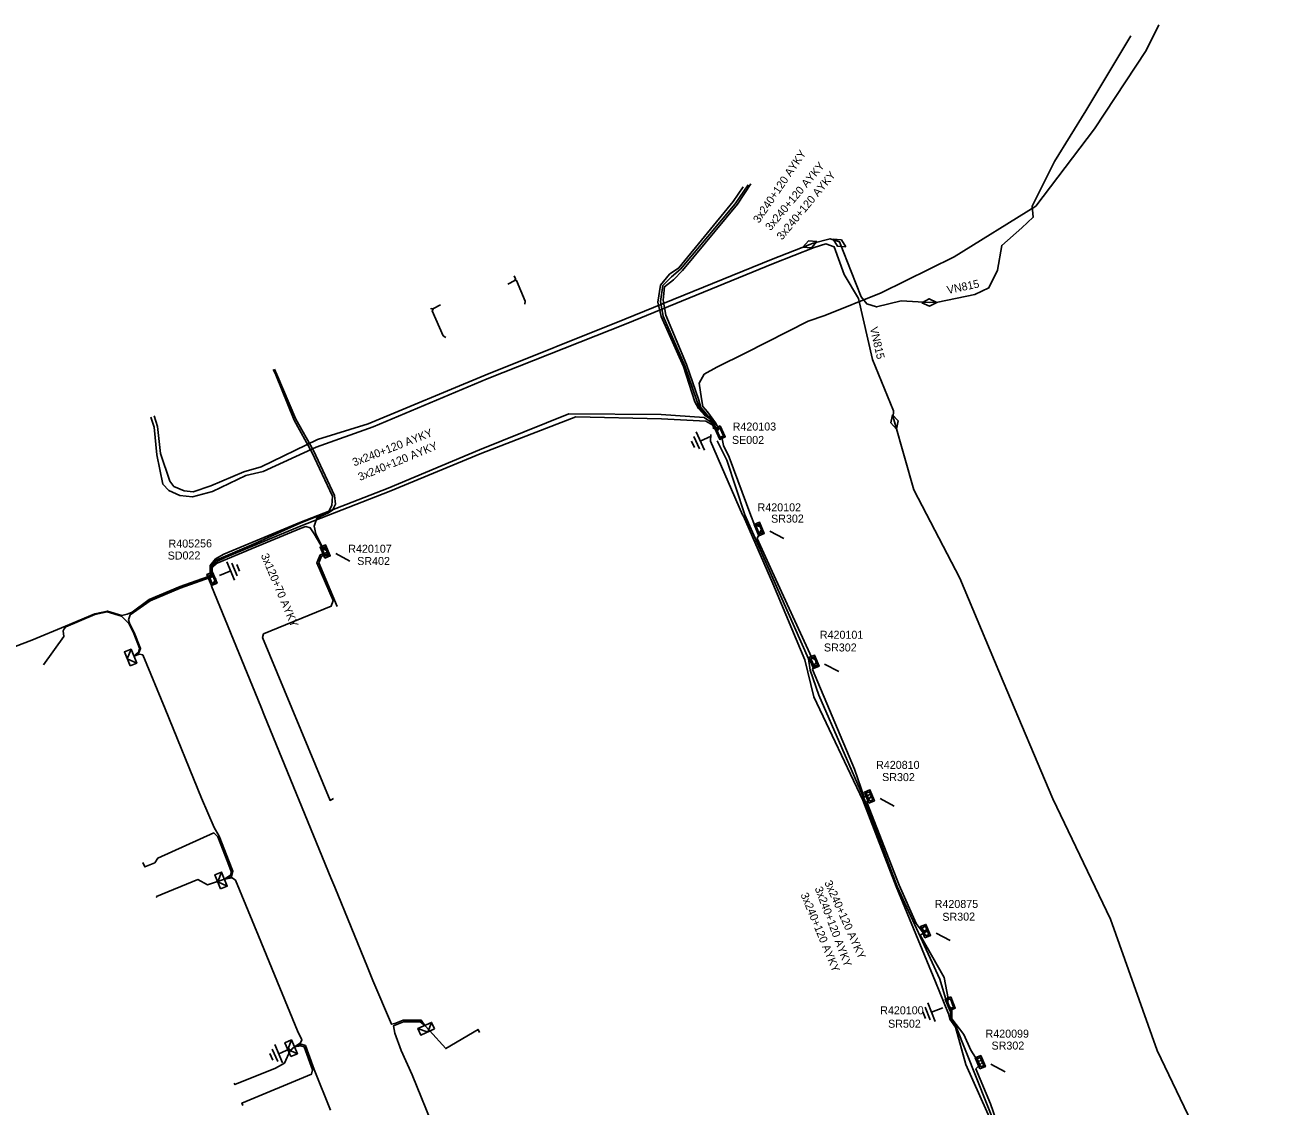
# Model space of a CAD drawing. Extents: x -540028 to -538776, y -1157064 to -1155670.
# Drawn here: x -539610.5 to -539454.6, y -1155813.9 to -1155678.8 of the extents above; entities that cross this region are included whole.
import ezdxf

# ---------------------------------------------------------------- set-up
doc = ezdxf.new("R2010")
doc.units = 0
for name, color, linetype in [('Vrstva 15', 7, 'Continuous'), ('Vrstva 19', 7, 'Continuous'), ('Vrstva 2', 7, 'Continuous'), ('Vrstva 28', 7, 'Continuous'), ('Vrstva 29', 7, 'Continuous'), ('Vrstva 30', 7, 'Continuous'), ('Vrstva 31', 7, 'Continuous'), ('Vrstva 5', 7, 'Continuous'), ('Vrstva 52', 7, 'Continuous'), ('Vrstva 59', 7, 'Continuous'), ('Vrstva 6', 7, 'Continuous'), ('Vrstva 7', 7, 'Continuous')]:
    doc.layers.add(name, color=color, linetype=linetype)

# ---------------------------------------------------------------- blocks, each defined once
blk = doc.blocks.new('17')
at = {"layer": 'Vrstva 2'}
blk.add_lwpolyline([(-1.875, 0), (0, 0.9375), (1.875, 0), (0, -0.9375)], close=True, dxfattribs=at)
blk = doc.blocks.new('132')
at = {"layer": 'Vrstva 2'}
for points in [[(-1.5, 1.5), (1.5, 1.5), (1.5, 0), (-1.5, 0)], [(-1.1, 1.2), (1.1, 1.2), (1.1, 0.3), (-1.1, 0.3)]]:
    blk.add_lwpolyline(points, close=True, dxfattribs=at)
blk = doc.blocks.new('23')
at = {"layer": 'Vrstva 2'}
blk.add_lwpolyline([(1.875, -1.8), (-1.875, -1.8), (-1.875, 0), (1.875, 0)], close=True, dxfattribs=at)
blk.add_lwpolyline([(1.875, 0), (0, -1.8), (-1.875, 0)], dxfattribs=at)
blk = doc.blocks.new('11')
at = {"layer": 'Vrstva 2'}
for p, q in [((0, -4.3), (0, -1.3)), ((-2.5, -4.3), (2.5, -4.3)), ((-1.7, -5.3), (1.7, -5.3)), ((-0.9, -6.3), (0.9, -6.3))]:
    blk.add_line(p, q, dxfattribs=at)

msp = doc.modelspace()

# ---------------------------------------------------------------- linework, layer by layer
at = {"layer": 'Vrstva 5'}
for points in [[(-539468.86, -1155678.76), (-539470.45, -1155681.97), (-539476.89, -1155691.74), (-539484.25, -1155701.39), (-539494.42, -1155707.72), (-539503.56, -1155712.23), (-539510.61, -1155715.06), (-539512.66, -1155715.76), (-539520.48, -1155719.75), (-539524.11, -1155721.52), (-539525.68, -1155722.4), (-539526.28, -1155723.51), (-539526.02, -1155725.46), (-539525.83, -1155726.44), (-539525.25, -1155727.12), (-539524.27, -1155728.46), (-539523.83, -1155729.24), (-539524.12, -1155729.6)], [(-539497.53, -1155713.45), (-539496.48, -1155713.42), (-539491.84, -1155712.45), (-539490.09, -1155711.59), (-539489.04, -1155709.39), (-539488.49, -1155706.31), (-539485.99, -1155704.13), (-539484.55, -1155702.79), (-539484.68, -1155701.4), (-539481.91, -1155695.84), (-539478, -1155689.51), (-539472.36, -1155680.12)], [(-539524.39, -1155729.17), (-539524.4, -1155728.7), (-539525.01, -1155727.93), (-539525.64, -1155727.54), (-539526.4, -1155726.69), (-539526.82, -1155725.84), (-539528.25, -1155721.46), (-539531.05, -1155715.21), (-539531.46, -1155713.41), (-539531.13, -1155711.26), (-539530.01, -1155709.92), (-539528.83, -1155709.12), (-539522.06, -1155700.83), (-539520.8, -1155698.97)], [(-539520.17, -1155698.72), (-539521.79, -1155701.12), (-539528.61, -1155709.26), (-539529.76, -1155710.25), (-539530.84, -1155711.33), (-539531.13, -1155713.3), (-539530.78, -1155715.13), (-539528.1, -1155721.34), (-539526.59, -1155725.73), (-539526.24, -1155726.6), (-539525.49, -1155727.5), (-539524.94, -1155727.89), (-539524.37, -1155728.64), (-539524.35, -1155729.15)], [(-539524.31, -1155729.17), (-539524.34, -1155728.58), (-539524.88, -1155727.85), (-539525.36, -1155727.43), (-539526.09, -1155726.55), (-539526.34, -1155725.63), (-539527.9, -1155721.17), (-539530.47, -1155715.01), (-539530.81, -1155713.14), (-539530.61, -1155711.48), (-539529.52, -1155710.63), (-539528.39, -1155709.44), (-539521.49, -1155701.14), (-539519.85, -1155698.6)], [(-539512.46, -1155706.18), (-539512.05, -1155706.02), (-539509.94, -1155705.47), (-539508.76, -1155705.88), (-539508.68, -1155706.08)], [(-539501.89, -1155728.36), (-539502.06, -1155727.76), (-539502.01, -1155726.97), (-539504.63, -1155720.56), (-539506.39, -1155712.94), (-539508.2, -1155709.96), (-539509.43, -1155706.47), (-539510.46, -1155706.12), (-539511.93, -1155706.57), (-539516.99, -1155708.58), (-539535.42, -1155716.09), (-539552.79, -1155723), (-539567.02, -1155728.99), (-539574.14, -1155731.51), (-539580.78, -1155734.54), (-539582.92, -1155735.05), (-539587.1, -1155737.06), (-539589.6, -1155737.71), (-539591.2, -1155737.58), (-539592.57, -1155736.94), (-539593.29, -1155736.16), (-539594.06, -1155732.47), (-539594.41, -1155729.04), (-539594.8, -1155727.76)], [(-539594.37, -1155727.6), (-539593.97, -1155728.94), (-539593.6, -1155732.32), (-539592.45, -1155735.75), (-539591.92, -1155736.44), (-539590.63, -1155736.96), (-539589.53, -1155737.11), (-539587.3, -1155736.36), (-539583.19, -1155734.59), (-539581.03, -1155733.98), (-539573.97, -1155730.58), (-539567.65, -1155728.6), (-539553.04, -1155722.51), (-539535.59, -1155715.53), (-539517.24, -1155708.08), (-539512.46, -1155706.18)], [(-539508.68, -1155706.08), (-539507.32, -1155709.55), (-539506.06, -1155712.73), (-539505.37, -1155713.61), (-539504.13, -1155714), (-539501.06, -1155713.25), (-539497.53, -1155713.45)], [(-539549.4, -1155710.1), (-539549.23, -1155710.48), (-539549.32, -1155710.67), (-539549.12, -1155710.69), (-539548.03, -1155713.28)], [(-539558.27, -1155717.61), (-539559.67, -1155714.48), (-539559.49, -1155714.21), (-539559.79, -1155714.22), (-539559.83, -1155714.15)], [(-539579.53, -1155721.82), (-539579.21, -1155722.49), (-539576.9, -1155728.13), (-539574.68, -1155732.16), (-539572.12, -1155737.66), (-539572.19, -1155738.79), (-539572.62, -1155739.58), (-539576.06, -1155740.99), (-539582.28, -1155743.76), (-539586.65, -1155745.66), (-539587.31, -1155746.42), (-539587.29, -1155747.24), (-539587.09, -1155747.35), (-539587.02, -1155747.32)], [(-539579.37, -1155721.76), (-539579.05, -1155722.43), (-539576.71, -1155728.01), (-539574.49, -1155731.93), (-539571.85, -1155737.55), (-539571.72, -1155738.64), (-539572.09, -1155739.4), (-539572.59, -1155739.73), (-539574.06, -1155740.4), (-539574.41, -1155741.39), (-539574.21, -1155742.34), (-539573.37, -1155744), (-539572.73, -1155744.35)], [(-539524.41, -1155729.18), (-539524.46, -1155728.7), (-539524.76, -1155728.42), (-539525.69, -1155727.81), (-539531.04, -1155727.45), (-539542.57, -1155727.37), (-539553.73, -1155731.87), (-539565.17, -1155736.65), (-539576.17, -1155740.92), (-539585.67, -1155744.89), (-539586.72, -1155745.46), (-539587.4, -1155746.32), (-539587.38, -1155747.19), (-539587.07, -1155747.41), (-539586.99, -1155747.38)], [(-539524.54, -1155729.23), (-539524.49, -1155729.15), (-539524.61, -1155728.75), (-539525.47, -1155728.28), (-539531.01, -1155727.98), (-539541.7, -1155727.74), (-539553.45, -1155732.27), (-539565.03, -1155737.04), (-539576.03, -1155741.33), (-539585.5, -1155745.29), (-539586.56, -1155745.82), (-539587.22, -1155746.59), (-539587.18, -1155747.04), (-539587.14, -1155747.14), (-539587.11, -1155747.17)], [(-539450.64, -1155871.22), (-539448.38, -1155870.37), (-539445.91, -1155869.51), (-539445.16, -1155868.63), (-539444.2, -1155867.88), (-539444.08, -1155866.88), (-539445.32, -1155863.06), (-539447.87, -1155858.8), (-539451.16, -1155849.36), (-539456.5, -1155836.11), (-539463.8, -1155817.93), (-539469.08, -1155806.9), (-539474.9, -1155790.51), (-539482.11, -1155775.46), (-539488.3, -1155760.82), (-539493.72, -1155747.89), (-539499.46, -1155736.84), (-539501.89, -1155728.36)], [(-539487.91, -1155820.03), (-539492.98, -1155808.65), (-539494.29, -1155804), (-539494.99, -1155803), (-539495.16, -1155802.35), (-539496.77, -1155798.32), (-539501.7, -1155786.4), (-539505.84, -1155775.62), (-539511.98, -1155762.7), (-539513.08, -1155758.08), (-539517.09, -1155748.54), (-539520.74, -1155740.13), (-539520.87, -1155739.97), (-539524.87, -1155730.77), (-539524.85, -1155729.93)], [(-539518.52, -1155741.52), (-539519.38, -1155741.23), (-539519.84, -1155740.06), (-539522.55, -1155732.78), (-539523.27, -1155731.32), (-539523.44, -1155730.47), (-539523.94, -1155729.99)], [(-539524.05, -1155730.71), (-539522.86, -1155733.16), (-539520.58, -1155739.97), (-539512.64, -1155757.97), (-539512.43, -1155759.39), (-539511.36, -1155762.53), (-539505.62, -1155775.68), (-539501.55, -1155786.41), (-539496.23, -1155797.99), (-539495.41, -1155800.77)], [(-539572.68, -1155744.48), (-539573.27, -1155744.25), (-539574.38, -1155742.37), (-539574.89, -1155741.59), (-539575.43, -1155741.45), (-539576.04, -1155741.66), (-539582.15, -1155744.18), (-539586.52, -1155746.02), (-539587.16, -1155746.58), (-539587.15, -1155747.08), (-539587.12, -1155747.1)], [(-539511.67, -1155758.13), (-539512.23, -1155757.85), (-539517.17, -1155747.04), (-539519.05, -1155742.95), (-539518.45, -1155741.7)], [(-539586.96, -1155747.46), (-539587, -1155747.48), (-539591.15, -1155748.94), (-539595.01, -1155750.56), (-539597.12, -1155752.13), (-539597.76, -1155752.38), (-539598.44, -1155752.54), (-539600.23, -1155752), (-539601.81, -1155752.35), (-539605.48, -1155753.89), (-539609.69, -1155755.65), (-539615.1, -1155757.69)], [(-539586.81, -1155747.59), (-539591.15, -1155749.14), (-539594.9, -1155750.72), (-539597.38, -1155752.46), (-539597.59, -1155753.08), (-539597.48, -1155753.52), (-539596.9, -1155754.66), (-539596.08, -1155756.66), (-539596.3, -1155757.2), (-539596.92, -1155757.63), (-539596.23, -1155757.39), (-539595.82, -1155757.49), (-539593.02, -1155764.23), (-539588.47, -1155775.39), (-539586.88, -1155779.05), (-539586.25, -1155780.12), (-539585.02, -1155783.33), (-539584.57, -1155784.51), (-539584.71, -1155785.2), (-539585.61, -1155785.49), (-539584.65, -1155785.35), (-539584.21, -1155785.64), (-539581.36, -1155792.58), (-539578.71, -1155799.08), (-539576.48, -1155804.44), (-539575.93, -1155805.56), (-539576.09, -1155805.97), (-539576.86, -1155806.46), (-539576.03, -1155806.13), (-539575.5, -1155806.3), (-539574.42, -1155809.28), (-539572.35, -1155814.38)], [(-539559.28, -1155817.03), (-539562.16, -1155809.96), (-539563.51, -1155806.9), (-539564.33, -1155804.74), (-539564.49, -1155803.85), (-539563.24, -1155803.33), (-539561.14, -1155803.34), (-539560.58, -1155803.78), (-539561.02, -1155803.14), (-539563.28, -1155803.13), (-539564.31, -1155803.53), (-539564.75, -1155803.64), (-539567.05, -1155798.18), (-539567.75, -1155796.49), (-539571.82, -1155786.5), (-539572.3, -1155785.33), (-539580.59, -1155765.09), (-539581.07, -1155763.93), (-539587.21, -1155748.88), (-539586.66, -1155747.94)], [(-539504.78, -1155774.85), (-539505.69, -1155775.25), (-539506.88, -1155771.75), (-539512.15, -1155759.3), (-539511.88, -1155758.72), (-539511.59, -1155758.31)], [(-539497.73, -1155791.78), (-539498.45, -1155792.04), (-539499.18, -1155791.03), (-539501.33, -1155786.24), (-539505.37, -1155775.88), (-539504.72, -1155775.01)], [(-539495.32, -1155801.01), (-539495.26, -1155800.99), (-539495.17, -1155800.41), (-539495.69, -1155797.79), (-539498.7, -1155792.48), (-539497.68, -1155791.92)], [(-539490.88, -1155808.16), (-539491.47, -1155808.23), (-539492.36, -1155806.88), (-539493.24, -1155804.91), (-539494.74, -1155802.94), (-539494.72, -1155802.01), (-539495, -1155801.44), (-539495.24, -1155801.11), (-539495.28, -1155801.12)], [(-539494.98, -1155801.92), (-539494.9, -1155802.1), (-539494.9, -1155802.94), (-539494.17, -1155803.94), (-539487.8, -1155819.99), (-539486.51, -1155822.3), (-539485.16, -1155826.12), (-539484.76, -1155827.34), (-539480.87, -1155836.78), (-539479.08, -1155841.24), (-539478.26, -1155843.91), (-539475.43, -1155849.76), (-539472.96, -1155857.03), (-539471.7, -1155859.83), (-539470.88, -1155862.16), (-539466.46, -1155870.57), (-539465.04, -1155874), (-539463.95, -1155878.02), (-539463.54, -1155878.76), (-539463.03, -1155879.5), (-539460.34, -1155879.4), (-539458.72, -1155878.71), (-539457.35, -1155877.87)], [(-539483.78, -1155825.14), (-539484.86, -1155826.29), (-539485.63, -1155822.68), (-539486.57, -1155820.89), (-539487.69, -1155819.94), (-539489.88, -1155813.58), (-539491.73, -1155809.19), (-539490.82, -1155808.29)]]:
    msp.add_lwpolyline(points, dxfattribs=at)
at = {"layer": 'Vrstva 52'}
for points in [[(-539572.59, -1155744.61), (-539573.63, -1155744.99), (-539574.05, -1155745.99), (-539572.04, -1155750.69), (-539572.29, -1155751.4), (-539580.71, -1155754.85), (-539580.85, -1155755.31), (-539572.42, -1155775.66), (-539571.97, -1155775.42)], [(-539572.52, -1155744.79), (-539573.48, -1155745.15), (-539573.83, -1155745.99), (-539571.52, -1155751.41)], [(-539596.92, -1155757.63), (-539596.35, -1155757.12), (-539596.22, -1155756.63), (-539596.95, -1155754.8), (-539597.56, -1155753.57), (-539598.48, -1155752.63), (-539600.26, -1155752.09), (-539601.82, -1155752.43), (-539605.44, -1155753.97), (-539605.65, -1155754.2), (-539605.74, -1155754.46), (-539605.68, -1155755.17), (-539608.2, -1155758.72)], [(-539585.61, -1155785.49), (-539584.82, -1155784.96), (-539584.77, -1155784.53), (-539585.2, -1155783.41), (-539586.43, -1155780.2), (-539586.93, -1155779.73), (-539593.95, -1155782.86), (-539594.31, -1155783.48), (-539595.54, -1155783.98), (-539595.8, -1155783.44)], [(-539585.61, -1155785.49), (-539587.71, -1155786.21), (-539588.94, -1155785.55), (-539594.09, -1155787.66), (-539594.07, -1155787.81)], [(-539560.58, -1155803.78), (-539559.98, -1155804.41), (-539557.97, -1155806.68), (-539553.92, -1155804.27), (-539553.74, -1155804.65)], [(-539576.86, -1155806.46), (-539577.39, -1155806.91), (-539578.12, -1155808.51), (-539579.24, -1155809.13), (-539584.3, -1155811.18), (-539584.39, -1155810.98)], [(-539576.86, -1155806.46), (-539576.05, -1155806.32), (-539575.66, -1155806.46), (-539574.6, -1155809.34), (-539574.72, -1155809.86), (-539583.42, -1155813.48), (-539583.32, -1155813.77)]]:
    msp.add_lwpolyline(points, dxfattribs=at)
at = {"layer": 'Vrstva 59'}
for points in [[(-539549.32, -1155710.68), (-539550.19, -1155711.17)], [(-539548.03, -1155713.28), (-539548.06, -1155713.64)], [(-539559.49, -1155714.21), (-539558.61, -1155713.73)], [(-539558.27, -1155717.61), (-539557.96, -1155717.83)], [(-539517.48, -1155742), (-539515.71, -1155742.93)], [(-539571.7, -1155744.82), (-539569.93, -1155745.75)], [(-539510.62, -1155758.62), (-539508.85, -1155759.54)], [(-539503.7, -1155775.43), (-539501.93, -1155776.36)], [(-539496.7, -1155792.24), (-539494.93, -1155793.17)], [(-539489.84, -1155808.63), (-539488.07, -1155809.56)]]:
    msp.add_lwpolyline(points, dxfattribs=at)

# ---------------------------------------------------------------- block references
at = {"layer": 'Vrstva 15'}
for p, xscale, yscale, rotation in [((-539524.2, -1155729.87), 0.5, 0.5000000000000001, -65.74232222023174), ((-539586.81, -1155747.82), 0.49999999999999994, 0.5000000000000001, 112.72487779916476), ((-539495.27, -1155801.32), 0.4999999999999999, 0.5000000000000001, -68.26976662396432), ((-539576.86, -1155806.46), 0.5, 0.5, -66.60629996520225)]:
    msp.add_blockref('11', p, dxfattribs=dict(at, xscale=xscale, yscale=yscale, rotation=rotation))
at = {"layer": 'Vrstva 19'}
for p, xscale, yscale, rotation in [((-539512.46, -1155706.18), 0.5, 0.5, -157.69353480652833), ((-539508.76, -1155706.02), 0.49999999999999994, 0.5000000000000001, 148.7258693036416), ((-539497.53, -1155713.45), 0.5, 0.49999999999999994, 1.640541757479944), ((-539501.89, -1155728.36), 0.5, 0.5000000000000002, -74.01295277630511)]:
    msp.add_blockref('17', p, dxfattribs=dict(at, xscale=xscale, yscale=yscale, rotation=rotation))
at = {"layer": 'Vrstva 28'}
for p, xscale, yscale, rotation in [((-539524.03, -1155729.86), 0.5, 0.5000000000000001, -65.74232222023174), ((-539518.46, -1155741.6), 0.5, 0.5, 112.92165560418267), ((-539572.68, -1155744.42), 0.5, 0.5, 112.77187223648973), ((-539586.81, -1155747.82), 0.49999999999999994, 0.5, 112.6198638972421), ((-539511.6, -1155758.21), 0.5, 0.5, 112.39759716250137), ((-539504.68, -1155775.02), 0.5, 0.49999999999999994, 112.41316391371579), ((-539497.68, -1155791.84), 0.5000000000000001, 0.5, 112.71026113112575), ((-539495.27, -1155801.2), 0.4999999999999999, 0.5000000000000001, -68.26976662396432), ((-539490.82, -1155808.23), 0.5, 0.5000000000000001, 112.52017222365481)]:
    msp.add_blockref('132', p, dxfattribs=dict(at, xscale=xscale, yscale=yscale, rotation=rotation))
at = {"layer": 'Vrstva 31', "xscale": 0.5, "yscale": 0.5}
for p, rotation in [((-539596.92, -1155757.63), -67.76199163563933), ((-539585.61, -1155785.49), -67.9621304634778), ((-539560.58, -1155803.78), 23.838394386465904), ((-539576.86, -1155806.45), -66.60630002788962)]:
    msp.add_blockref('23', p, dxfattribs=dict(at, rotation=rotation))

# ---------------------------------------------------------------- texts
at = {"layer": 'Vrstva 29'}
for s, p in [('R420103', (-539522.11, -1155729.44)), ('R420102', (-539519, -1155739.54)), ('R420107', (-539570.14, -1155744.71)), ('R420101', (-539511.22, -1155755.46)), ('R420810', (-539504.19, -1155771.72)), ('R420875', (-539496.87, -1155789.1)), ('R420100', (-539503.68, -1155802.39)), ('R420099', (-539490.52, -1155805.31))]:
    msp.add_text(s, height=1, dxfattribs=at).set_placement(p)
msp.add_text('R405256', height=1, rotation=0.428, dxfattribs=at).set_placement((-539592.59, -1155744.08))
at = {"layer": 'Vrstva 30'}
for s, rotation, p in [('SE002', 359.886, (-539522.2, -1155731.11)), ('SR302', 0.28, (-539517.31, -1155740.96)), ('SD022', 0.428, (-539592.7, -1155745.57)), ('SR402', 0.127, (-539569.02, -1155746.25)), ('SR302', 359.971, (-539510.71, -1155757.05)), ('SR302', 359.786, (-539503.44, -1155773.24)), ('SR302', 0.599, (-539495.91, -1155790.71)), ('SR502', 0.177, (-539502.69, -1155804.07)), ('SR302', 0.096, (-539489.77, -1155806.8))]:
    msp.add_text(s, height=1, rotation=rotation, dxfattribs=at).set_placement(p)
at = {"layer": 'Vrstva 6'}
for s, rotation, p in [('3x240+120 AYKY', 55.842, (-539518.82, -1155703.6)), ('3x240+120 AYKY', 49.98, (-539517.38, -1155704.54)), ('3x240+120 AYKY', 50.281, (-539515.95, -1155705.71)), ('3x240+120 AYKY', 21.189, (-539569.39, -1155733.93)), ('3x240+120 AYKY', 22.409, (-539568.67, -1155735.75)), ('3x120+70 AYKY', 292.87, (-539581.08, -1155745.04)), ('3x240+120 AYKY', 290.752, (-539511.88, -1155786.65)), ('3x240+120 AYKY', 294.154, (-539510.68, -1155785.92)), ('3x240+120 AYKY', 292.472, (-539513.65, -1155787.43))]:
    msp.add_text(s, height=1, rotation=rotation, dxfattribs=at).set_placement(p)
at = {"layer": 'Vrstva 7'}
for rotation, p in [(11.826, (-539495.23, -1155712.38)), (282.973, (-539504.98, -1155716.62))]:
    msp.add_text('VN815', height=1, rotation=rotation, dxfattribs=at).set_placement(p)

doc.saveas('drawing.dxf')
